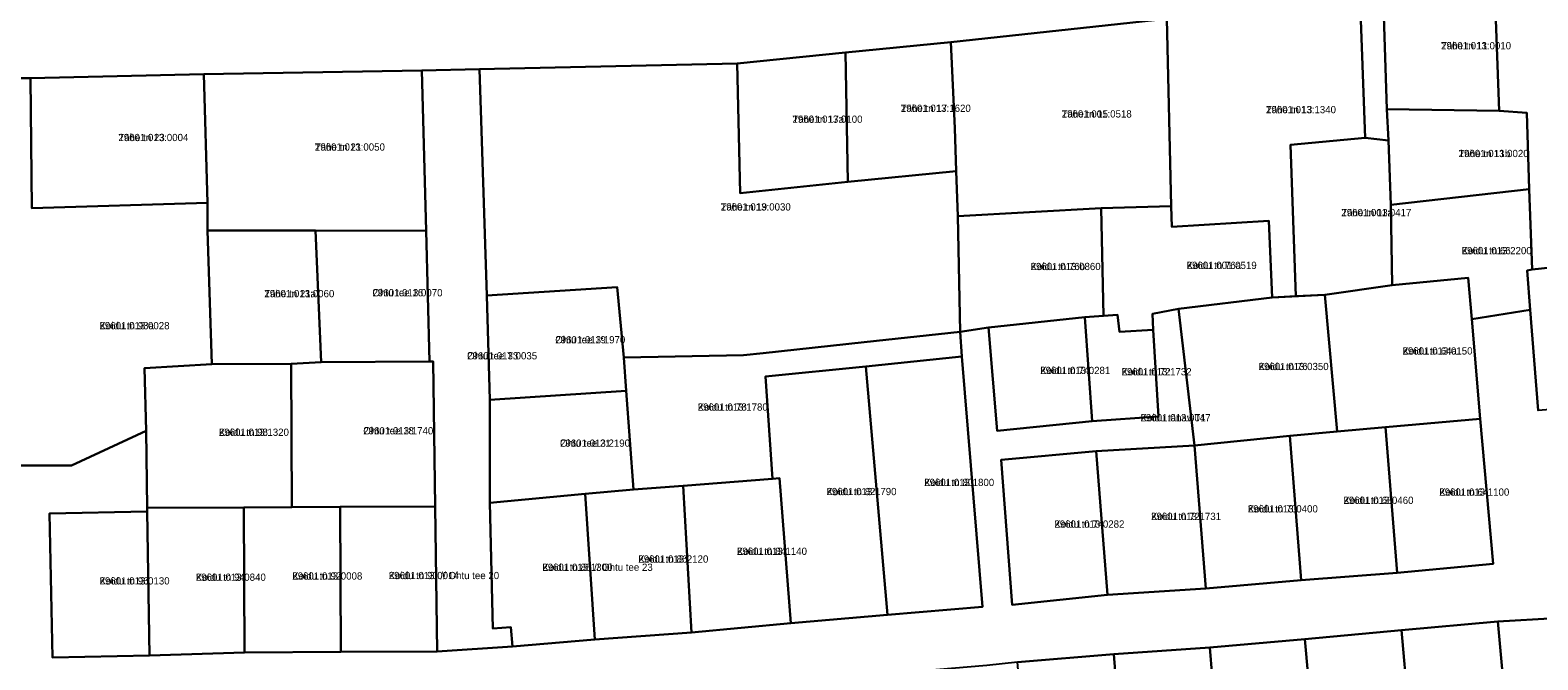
# Model space of a CAD drawing. Extents: x 518839 to 525192, y 6573164 to 6576561.
# Drawn here: x 523676 to 523988.3, y 6573878.1 to 6574008.4 of the extents above; entities that cross this region are included whole.
import ezdxf

# ---------------------------------------------------------------- set-up
doc = ezdxf.new("R2010")
doc.units = 0
for name, color, linetype in [('L_AADRESS', 7, 'Continuous'), ('PIIR', 7, 'Continuous'), ('TUNNUS', 7, 'Continuous')]:
    doc.layers.add(name, color=color, linetype=linetype)

msp = doc.modelspace()

# ---------------------------------------------------------------- linework, layer by layer
at = {"layer": 'PIIR'}
for points in [[(523956.21, 6574015.69), (523979.32, 6574018.22), (523980.25, 6573991.75), (523956.97, 6573992.05)], [(523986.5, 6573975.48), (523986.02, 6573991.28), (523980.25, 6573991.75), (523979.32, 6574018.22), (524001.33, 6574020.4), (524002.35, 6573989.41), (524003.19, 6573960.61), (523987.11, 6573958.88)], [(523912.33, 6573972.02), (523911.44, 6574010.74), (523951.42, 6574016.19), (523952.49, 6573986.17), (523937.04, 6573984.67), (523938.18, 6573953.35), (523933.24, 6573953.09), (523932.55, 6573968.95), (523912.44, 6573967.71)], [(523867.49, 6573988.11), (523866.69, 6574005.94), (523911.44, 6574010.74), (523912.33, 6573972.02), (523897.81, 6573971.55), (523868.11, 6573969.95), (523867.78, 6573979.24)], [(523845.34, 6573977.01), (523844.87, 6574003.78), (523866.69, 6574005.94), (523867.49, 6573988.11), (523867.78, 6573979.24)], [(523823.06, 6573974.71), (523822.44, 6574001.53), (523844.87, 6574003.78), (523845.34, 6573977.01)], [(523711.94, 6573999.34), (523712.69, 6573972.67), (523676.34, 6573971.58), (523676.04, 6573998.47)], [(523712.69, 6573972.67), (523711.94, 6573999.34), (523757.1, 6574000.06), (523758, 6573966.91), (523735.07, 6573966.93), (523712.7, 6573966.98)], [(523757.1, 6574000.06), (523769.06, 6574000.36), (523770.55, 6573953.49), (523771.2, 6573931.92), (523771.19, 6573910.59), (523771.81, 6573884.56), (523775.58, 6573884.84), (523775.89, 6573880.85), (523760.31, 6573879.83), (523759.91, 6573909.83), (523759.46, 6573939.83), (523758.73, 6573939.83), (523758, 6573966.91)], [(523770.55, 6573953.49), (523769.06, 6574000.36), (523822.44, 6574001.53), (523823.06, 6573974.71), (523845.34, 6573977.01), (523867.78, 6573979.24), (523868.11, 6573969.95), (523868.61, 6573945.96), (523848.71, 6573943.83), (523827.82, 6573941.59), (523823.74, 6573941.15), (523798.95, 6573940.64), (523797.61, 6573955.26)], [(523670.16, 6573998.46), (523676.04, 6573998.47), (523676.34, 6573971.58), (523712.69, 6573972.67), (523712.7, 6573966.98), (523713.63, 6573939.28), (523699.65, 6573938.45), (523700.01, 6573925.48), (523684.56, 6573918.33), (523667.5, 6573918.29), (523667.09, 6573938.18), (523671.15, 6573938.46)], [(523956.97, 6573992.05), (523980.25, 6573991.75), (523986.02, 6573991.28), (523986.5, 6573975.48), (523957.85, 6573972.25), (523957.31, 6573985.62)], [(523944.13, 6573953.67), (523938.18, 6573953.35), (523937.04, 6573984.67), (523952.49, 6573986.17), (523957.31, 6573985.62), (523957.85, 6573972.25), (523958.1, 6573955.63)], [(523958.1, 6573955.63), (523957.85, 6573972.25), (523986.5, 6573975.48), (523987.11, 6573958.88), (523986.06, 6573958.7), (523986.71, 6573950.55), (523974.57, 6573948.61), (523973.82, 6573957.18)], [(523868.61, 6573945.96), (523868.11, 6573969.95), (523897.81, 6573971.55), (523898.32, 6573949.3), (523894.41, 6573949.04), (523874.47, 6573946.91)], [(523898.32, 6573949.3), (523897.81, 6573971.55), (523912.33, 6573972.02), (523912.44, 6573967.71), (523932.55, 6573968.95), (523933.24, 6573953.09), (523913.82, 6573950.74), (523908.46, 6573949.72), (523908.6, 6573946.42), (523901.64, 6573945.97), (523901.2, 6573949.53)], [(523712.7, 6573966.98), (523735.07, 6573966.93), (523736.27, 6573939.67), (523730.08, 6573939.36), (523713.63, 6573939.28)], [(523735.07, 6573966.93), (523758, 6573966.91), (523758.73, 6573939.83), (523736.27, 6573939.67)], [(523986.71, 6573950.55), (523986.06, 6573958.7), (523987.11, 6573958.88), (524003.19, 6573960.61), (524015.9, 6573962.16), (524018.83, 6573932.16), (524007.73, 6573931.26), (523988.32, 6573929.69)], [(523770.55, 6573953.49), (523797.61, 6573955.26), (523798.95, 6573940.64), (523799.45, 6573933.78), (523771.2, 6573931.92)], [(523946.74, 6573925.38), (523944.13, 6573953.67), (523958.1, 6573955.63), (523973.82, 6573957.18), (523974.57, 6573948.61), (523976.35, 6573927.95), (523956.7, 6573926.24)], [(523917.16, 6573922.45), (523913.82, 6573950.74), (523933.24, 6573953.09), (523944.13, 6573953.67), (523946.74, 6573925.38), (523936.87, 6573924.44)], [(523874.47, 6573946.91), (523894.41, 6573949.04), (523895.95, 6573927.5), (523876.26, 6573925.52)], [(523895.95, 6573927.5), (523894.41, 6573949.04), (523898.32, 6573949.3), (523901.2, 6573949.53), (523901.64, 6573945.97), (523908.6, 6573946.42), (523909.71, 6573928.48)], [(523799.45, 6573933.78), (523798.95, 6573940.64), (523823.74, 6573941.15), (523827.82, 6573941.59), (523848.71, 6573943.83), (523868.61, 6573945.96), (523868.99, 6573940.86), (523849.09, 6573938.83), (523828.31, 6573936.7), (523829.77, 6573915.53), (523811.25, 6573914.13), (523800.93, 6573913.36)], [(523759.46, 6573939.83), (523759.91, 6573909.83), (523740.22, 6573909.74), (523730.22, 6573909.7), (523730.08, 6573939.36), (523736.27, 6573939.67), (523758.73, 6573939.83)], [(523853.56, 6573887.43), (523849.09, 6573938.83), (523868.99, 6573940.86), (523873.24, 6573889.03)], [(523713.63, 6573939.28), (523730.08, 6573939.36), (523730.22, 6573909.7), (523720.23, 6573909.62), (523700.23, 6573909.53), (523700.01, 6573925.48), (523699.65, 6573938.45)], [(523829.77, 6573915.53), (523828.31, 6573936.7), (523849.09, 6573938.83), (523853.56, 6573887.43), (523833.53, 6573885.7), (523831.18, 6573915.69)], [(523771.2, 6573931.92), (523799.45, 6573933.78), (523800.93, 6573913.36), (523790.95, 6573912.44), (523771.19, 6573910.59)], [(523956.7, 6573926.24), (523976.35, 6573927.95), (523979.02, 6573897.99), (523959.16, 6573896.07)], [(523919.5, 6573892.85), (523917.16, 6573922.45), (523936.87, 6573924.44), (523939.24, 6573894.58)], [(523939.24, 6573894.58), (523936.87, 6573924.44), (523946.74, 6573925.38), (523956.7, 6573926.24), (523959.16, 6573896.07)], [(523877.13, 6573919.46), (523896.81, 6573921.25), (523899.14, 6573891.57), (523879.38, 6573889.49)], [(523896.81, 6573921.25), (523917.16, 6573922.45), (523919.5, 6573892.85), (523899.14, 6573891.57)], [(523811.25, 6573914.13), (523829.77, 6573915.53), (523831.18, 6573915.69), (523833.53, 6573885.7), (523812.98, 6573883.77)], [(523775.58, 6573884.84), (523771.81, 6573884.56), (523771.19, 6573910.59), (523790.95, 6573912.44), (523792.98, 6573882.32), (523775.89, 6573880.85)], [(523792.98, 6573882.32), (523790.95, 6573912.44), (523800.93, 6573913.36), (523811.25, 6573914.13), (523812.98, 6573883.77)], [(523700.73, 6573879), (523680.64, 6573878.58), (523680.01, 6573908.35), (523700.23, 6573908.79)], [(523700.73, 6573879), (523700.23, 6573908.79), (523700.23, 6573909.53), (523720.23, 6573909.62), (523720.37, 6573879.63)], [(523720.37, 6573879.63), (523720.23, 6573909.62), (523730.22, 6573909.7), (523740.22, 6573909.74), (523740.35, 6573879.74)], [(523760.31, 6573879.83), (523740.35, 6573879.74), (523740.22, 6573909.74), (523759.91, 6573909.83)], [(523979.96, 6573886.04), (523991.91, 6573886.74), (523993.87, 6573855.18), (523998.29, 6573812.14), (523999.71, 6573790.43), (524001.71, 6573769.87), (524004.3, 6573740.13), (523991.73, 6573738.64), (523989.14, 6573774.8), (523987.31, 6573795.12), (523985.77, 6573815.38), (523983.8, 6573835.68), (523982.65, 6573856.32)], [(523939.99, 6573882.39), (523960.05, 6573884.2), (523962.69, 6573854.45), (523953.25, 6573853.38), (523951.2, 6573853.15), (523942.71, 6573852.51)], [(523960.05, 6573884.2), (523979.96, 6573886.04), (523982.65, 6573856.32), (523962.69, 6573854.45)], [(523902.82, 6573849.39), (523900.44, 6573879.28), (523920.33, 6573880.66), (523922.76, 6573850.99), (523911.47, 6573849.94)], [(523920.33, 6573880.66), (523939.99, 6573882.39), (523942.71, 6573852.51), (523922.76, 6573850.99)], [(523880.51, 6573877.59), (523900.44, 6573879.28), (523902.82, 6573849.39), (523883.08, 6573847.7)]]:
    msp.add_lwpolyline(points, close=True, dxfattribs=at)
for points in [[(523956.21, 6574015.69), (523956.97, 6573992.05), (523957.31, 6573985.62), (523952.49, 6573986.17), (523951.42, 6574016.19)], [(523911.44, 6574010.74), (523866.69, 6574005.94), (523844.87, 6574003.78), (523822.44, 6574001.53), (523769.06, 6574000.36), (523757.1, 6574000.06), (523711.94, 6573999.34), (523676.04, 6573998.47), (523670.16, 6573998.46)], [(523667.5, 6573918.29), (523684.56, 6573918.33), (523700.01, 6573925.48), (523700.23, 6573909.53), (523700.23, 6573908.79), (523680.01, 6573908.35), (523680.64, 6573878.58), (523700.73, 6573879), (523720.37, 6573879.63), (523740.35, 6573879.74), (523760.31, 6573879.83), (523775.89, 6573880.85), (523792.98, 6573882.32), (523812.98, 6573883.77), (523833.53, 6573885.7), (523853.56, 6573887.43), (523873.24, 6573889.03), (523868.99, 6573940.86), (523868.61, 6573945.96), (523874.47, 6573946.91), (523876.26, 6573925.52), (523895.95, 6573927.5), (523909.71, 6573928.48), (523908.6, 6573946.42), (523908.46, 6573949.72), (523913.82, 6573950.74), (523917.16, 6573922.45), (523896.81, 6573921.25), (523877.13, 6573919.46), (523879.38, 6573889.49), (523899.14, 6573891.57), (523919.5, 6573892.85), (523939.24, 6573894.58), (523959.16, 6573896.07), (523979.02, 6573897.99), (523976.35, 6573927.95), (523974.57, 6573948.61), (523986.71, 6573950.55), (523988.32, 6573929.69)], [(523991.91, 6573886.74), (523979.96, 6573886.04), (523960.05, 6573884.2), (523939.99, 6573882.39), (523920.33, 6573880.66), (523900.44, 6573879.28), (523880.51, 6573877.59), (523874.14, 6573876.88), (523853.82, 6573875.19), (523833.51, 6573873.42), (523813.6, 6573871.79), (523793.26, 6573870.36), (523771.87, 6573868.48), (523756.61, 6573868.23), (523740.59, 6573868.09), (523720.71, 6573867.39), (523700.81, 6573867.17), (523680.81, 6573866.98), (523669.79, 6573866.9)]]:
    msp.add_lwpolyline(points, dxfattribs=at)

# ---------------------------------------------------------------- texts
at = {"layer": 'L_AADRESS'}
for s, p in [('Tähe tn 11', (523968.23, 6574004.46)), ('Tähe tn 17', (523856.32, 6573991.51)), ('Tähe tn 13', (523931.96, 6573991.23)), ('Tähe tn 17a', (523833.89, 6573989.25)), ('Tähe tn 15', (523889.65, 6573990.34)), ('Tähe tn 23', (523694.26, 6573985.46)), ('Tähe tn 21', (523734.97, 6573983.49)), ('Tähe tn 11b', (523971.87, 6573982.15)), ('Tähe tn 19', (523819.03, 6573971.09)), ('Tähe tn 13a', (523947.57, 6573969.92)), ('Koidu tn 66', (523972.5, 6573962.04)), ('Koidu tn 76b', (523883.22, 6573958.76)), ('Koidu tn 76a', (523915.54, 6573958.99)), ('Tähe tn 21a', (523724.49, 6573953.14)), ('Ohtu tee 16', (523746.9, 6573953.33)), ('Koidu tn 98a', (523690.36, 6573946.51)), ('Ohtu tee 19', (523784.76, 6573943.59)), ('Koidu tn 64a', (523960.24, 6573941.28)), ('Ohtu tee T3', (523766.5, 6573940.27)), ('Koidu tn 74', (523885.21, 6573937.24)), ('Koidu tn 72', (523902.06, 6573936.97)), ('Koidu tn 76', (523930.44, 6573938.06)), ('Koidu tn 78', (523814.27, 6573929.66)), ('Koidu tänav T1', (523905.99, 6573927.45)), ('Koidu tn 98', (523715.09, 6573924.45)), ('Ohtu tee 18', (523744.99, 6573924.75)), ('Ohtu tee 21', (523785.74, 6573922.19)), ('Koidu tn 80', (523861.17, 6573914.06)), ('Koidu tn 82', (523840.94, 6573912.17)), ('Koidu tn 68', (523948.01, 6573910.36)), ('Koidu tn 64', (523967.86, 6573912.06)), ('Koidu tn 72', (523908.16, 6573907.03)), ('Koidu tn 70', (523928.2, 6573908.59)), ('Koidu tn 74', (523888.14, 6573905.44)), ('Koidu tn 86', (523801.96, 6573898.2)), ('Koidu tn 84', (523822.39, 6573899.81)), ('Koidu tn 94', (523710.3, 6573894.44)), ('Koidu tn 92', (523730.29, 6573894.69)), ('Koidu tn 90 // Ohtu tee 20', (523750.27, 6573894.79)), ('Koidu tn 88 // Ohtu tee 23', (523782.08, 6573896.5)), ('Koidu tn 96', (523690.37, 6573893.68))]:
    msp.add_text(s, height=1.5, dxfattribs=at).set_placement(p)
at = {"layer": 'TUNNUS'}
for s, p in [('29601:013:0010', (523968.23, 6574004.46)), ('29601:013:1620', (523856.32, 6573991.51)), ('29601:013:1340', (523931.96, 6573991.23)), ('29601:013:0100', (523833.89, 6573989.25)), ('29601:001:0518', (523889.65, 6573990.34)), ('29601:013:0004', (523694.26, 6573985.46)), ('29601:013:0050', (523734.97, 6573983.49)), ('29601:013:0020', (523971.87, 6573982.15)), ('29601:013:0030', (523819.03, 6573971.09)), ('29601:001:0417', (523947.57, 6573969.92)), ('29601:013:2200', (523972.5, 6573962.04)), ('29601:013:0860', (523883.22, 6573958.76)), ('29601:001:0519', (523915.54, 6573958.99)), ('29601:013:0060', (523724.49, 6573953.14)), ('29601:013:0070', (523746.9, 6573953.33)), ('29601:013:0028', (523690.36, 6573946.51)), ('29601:013:1970', (523784.76, 6573943.59)), ('29601:013:0150', (523960.24, 6573941.28)), ('29601:013:0035', (523766.5, 6573940.27)), ('29601:013:0281', (523885.21, 6573937.24)), ('29601:013:1732', (523902.06, 6573936.97)), ('29601:013:0350', (523930.44, 6573938.06)), ('29601:013:1780', (523814.27, 6573929.66)), ('29601:013:0047', (523905.99, 6573927.45)), ('29601:013:1320', (523715.09, 6573924.45)), ('29601:013:1740', (523744.99, 6573924.75)), ('29601:013:2190', (523785.74, 6573922.19)), ('29601:013:1800', (523861.17, 6573914.06)), ('29601:013:1790', (523840.94, 6573912.17)), ('29601:013:0460', (523948.01, 6573910.36)), ('29601:013:1100', (523967.86, 6573912.06)), ('29601:013:1731', (523908.16, 6573907.03)), ('29601:013:0400', (523928.2, 6573908.59)), ('29601:013:0282', (523888.14, 6573905.44)), ('29601:013:2120', (523801.96, 6573898.2)), ('29601:013:1140', (523822.39, 6573899.81)), ('29601:013:0840', (523710.3, 6573894.44)), ('29601:013:0008', (523730.29, 6573894.69)), ('29601:013:0014', (523750.27, 6573894.79)), ('29601:013:1300', (523782.08, 6573896.5)), ('29601:013:0130', (523690.37, 6573893.68))]:
    msp.add_text(s, height=1.5, dxfattribs=at).set_placement(p)

doc.saveas('drawing.dxf')
